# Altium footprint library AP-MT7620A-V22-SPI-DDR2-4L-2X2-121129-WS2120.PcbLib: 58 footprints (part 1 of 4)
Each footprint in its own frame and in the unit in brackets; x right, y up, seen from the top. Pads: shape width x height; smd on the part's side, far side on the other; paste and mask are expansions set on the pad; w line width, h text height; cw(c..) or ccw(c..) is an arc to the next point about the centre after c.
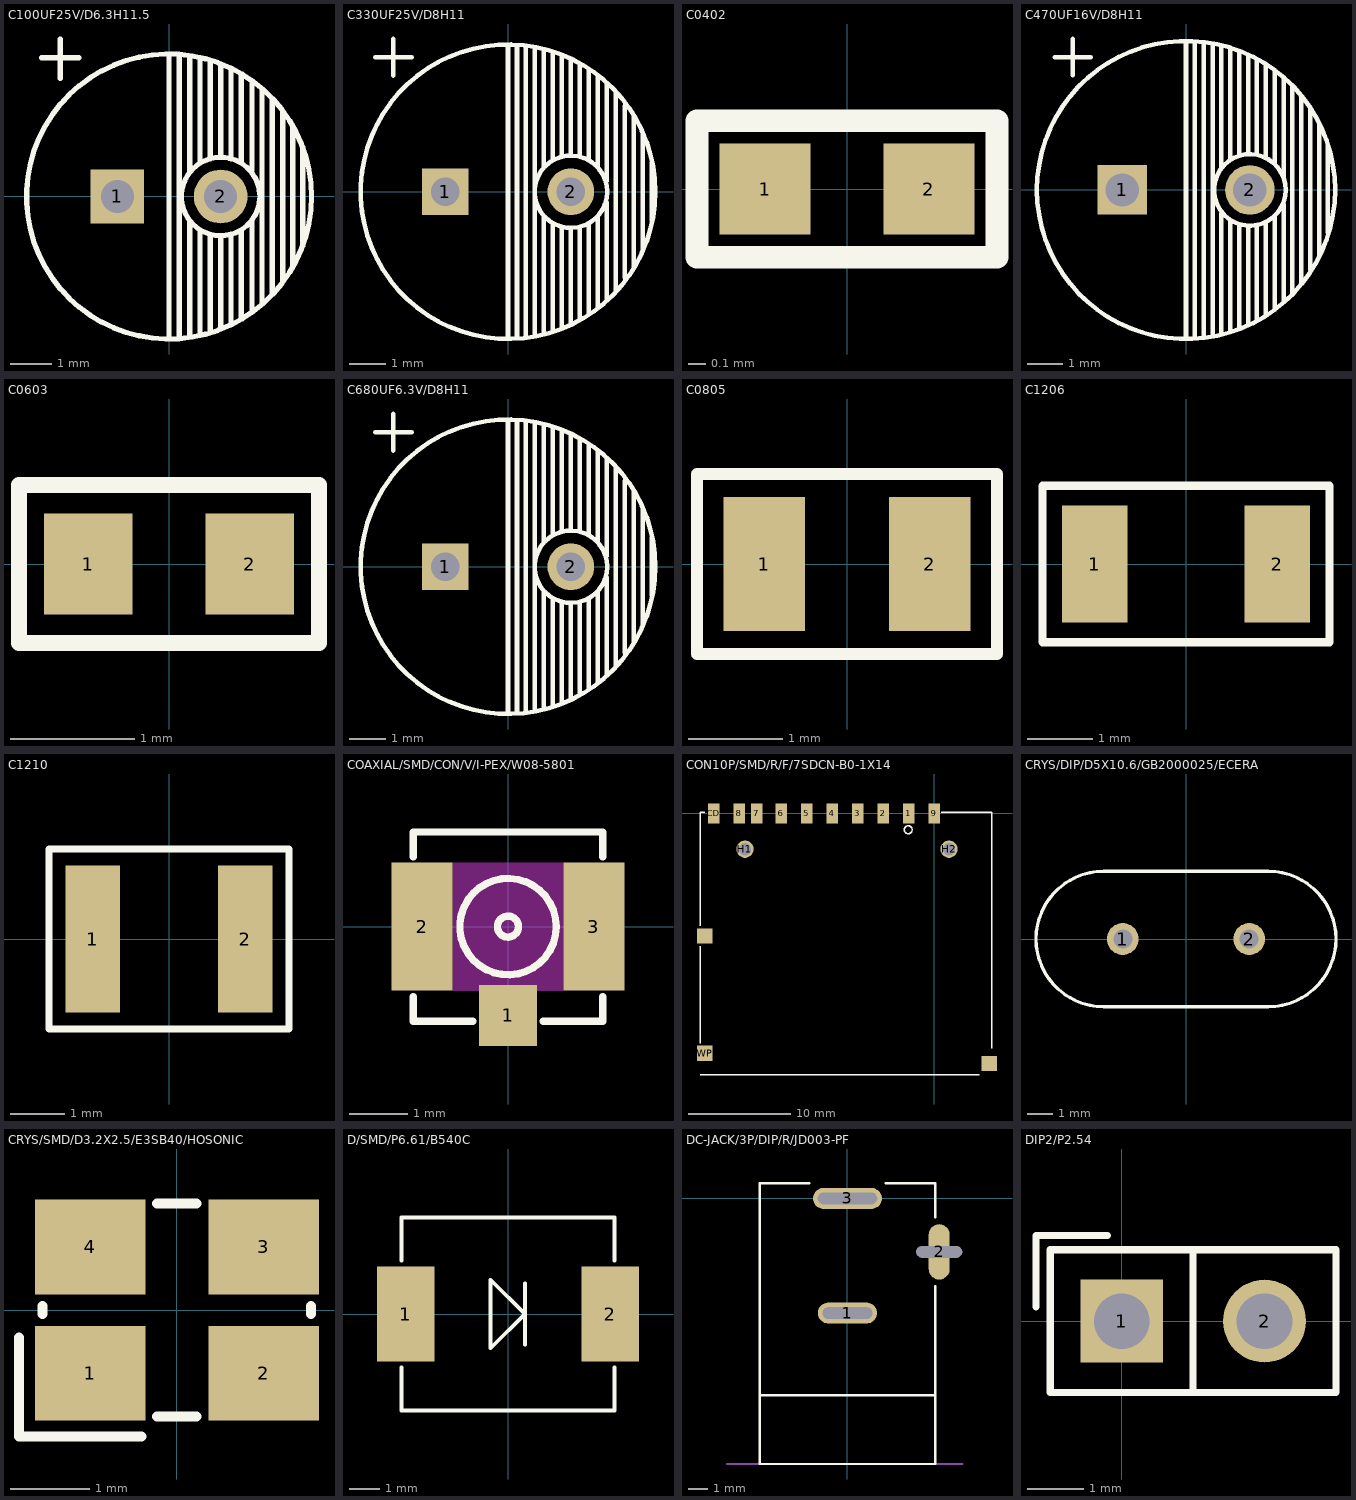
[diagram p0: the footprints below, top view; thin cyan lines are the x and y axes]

## C100UF25V/D6.3H11.5 [mm]
pads (2):
  rect 1.3x1.3 / inner round 1.3 / far side rect 1.3x1.3 hole 0.8: 1(-1.25,0)
  round 1.3 hole 0.8: 2(1.25,0)
Top Overlay:
  circle w0.127: c1.25,0 r0.95
  circle w0.127: c0,0 r3.45
  lines w0.127: -3.081,3.357 -2.181,3.357 ; -2.631,2.863 -2.631,3.813 ; 0,-3.4 0,3.4 ; 0.25,-3.37 0.25,3.37 ; 0.5,-3.35 0.5,-0.635 ; 0.5,0.61 0.5,3.35 ; 0.75,-3.3 0.75,-0.838 ; 0.75,0.838 0.75,3.3 ; 1,-3.25 1,-0.95 ; 1,0.914 1,3.25 ; 1.25,-3.2 1.25,-0.95 ; 1.25,1 1.25,3.2 ; 1.5,-3.1 1.5,-0.914 ; 1.5,0.914 1.5,3.1 ; 1.75,-2.95 1.75,-0.813 ; 1.75,0.813 1.75,2.95 ; 2.008,-2.8 2.008,-0.61 ; 2.008,0.635 2.008,2.8 ; 2.25,-2.55 2.25,2.55 ; 2.5,-2.35 2.5,2.35 ; 2.754,-2.05 2.754,2.05 ; 2.997,-1.7 2.997,1.7 ; 3.237,-1.2 3.237,1.2

## C330UF25V/D8H11 [mm]
pads (2):
  rect 1.3x1.3 / inner round 1.3 / far side rect 1.3x1.3 hole 0.8: 1(-1.75,0)
  round 1.3 hole 0.8: 2(1.75,0)
Top Overlay:
  circle w0.127: c0,0 r4.1
  circle w0.127: c1.75,0 r1.008
  lines w0.127: -3.698,3.745 -2.682,3.745 ; -3.19,3.237 -3.19,4.253 ; 0,-4.08 0,4.08 ; 0.25,-4.05 0.25,4.05 ; 0.5,-4.03 0.5,4.03 ; 0.75,-4 0.75,4 ; 1,-3.95 1,-0.7 ; 1,0.7 1,3.95 ; 1.25,-3.85 1.25,-0.9 ; 1.25,0.9 1.25,3.85 ; 1.5,-3.78 1.5,-1 ; 1.5,1 1.5,3.78 ; 1.75,-3.65 1.75,-1.05 ; 1.75,1.05 1.75,3.65 ; 2,-3.55 2,-1 ; 2,1 2,3.55 ; 2.25,-3.4 2.25,-0.9 ; 2.25,0.9 2.25,3.4 ; 2.5,-3.2 2.5,-0.7 ; 2.5,0.7 2.5,3.2 ; 2.75,-3 2.75,-0.3 ; 2.75,0.3 2.75,3 ; 3,-2.75 3,2.75 ; 3.25,-2.4 3.25,2.4 ; 3.5,-2.1 3.5,2.1 ; 3.75,-1.6 3.75,1.6 ; 4,-0.8 4,0.8

## C0402 [mil]
pads (2):
  rect 20x20 smd: 1(-18,0) 2(18,0)
Top Overlay:
  lines w5: -33,-15 -33,15 33,15 33,-15 -33,-15

## C470UF16V/D8H11 [mil]
pads (2):
  rect 55x55 / inner round 55 / far side rect 55x55 hole 37: 1(-70.87,0)
  round 55 hole 37: 2(70.87,0)
Top Overlay:
  circle w5: c0,0 r165.35
  circle w5: c70.87,0 r39.7
  lines w5: -145.59,147.44 -105.59,147.44 ; -125.59,127.44 -125.59,167.44 ; 0,-165 0,165 ; 9.84,-163.39 9.84,163.39 ; 19.68,-163.39 19.68,163.39 ; 29.53,-161.42 29.53,161.42 ; 39.37,-159.45 39.37,-25.59 ; 39.37,25.59 39.37,159.45 ; 49.21,-157.48 49.21,-33.46 ; 49.21,33.46 49.21,157.48 ; 59.06,-153.54 59.06,-39.37 ; 59.06,39.37 59.06,153.54 ; 68.9,-149.61 68.9,-41.34 ; 68.9,41.34 68.9,149.61 ; 78.74,-143.7 78.74,-39.37 ; 78.74,39.37 78.74,143.7 ; 88.58,-137.8 88.58,-35.43 ; 88.58,35.43 88.58,139.76 ; 98.43,-131.89 98.43,-29.53 ; 98.43,29.53 98.43,131.89 ; 108.27,-124.02 108.27,-15.75 ; 108.27,13.78 108.27,124.02 ; 118.11,-114.17 118.11,114.17 ; 127.95,-102.36 127.95,102.36 ; 137.8,-88.58 137.8,90.55 ; 147.64,-72.83 147.64,72.83 ; 157.48,-47.24 157.48,49.21

## C0603 [mil]
pads (2):
  rect 28x32 smd: 1(-25.59,0) 2(25.59,0)
Top Overlay:
  lines w5: -47.5,-25 47.5,-25 47.5,25 -47.5,25 -47.5,-25

## C680UF6.3V/D8H11 [mm]
pads (2):
  rect 1.3x1.3 / inner round 1.3 / far side rect 1.3x1.3 hole 0.8: 1(-1.75,0)
  round 1.3 hole 0.8: 2(1.75,0)
Top Overlay:
  circle w0.127: c0,0 r4.1
  circle w0.127: c1.75,0 r1.008
  lines w0.127: -3.698,3.745 -2.682,3.745 ; -3.19,3.237 -3.19,4.253 ; 0,-4.08 0,4.08 ; 0.25,-4.05 0.25,4.05 ; 0.5,-4.03 0.5,4.03 ; 0.75,-4 0.75,4 ; 1,-3.95 1,-0.7 ; 1,0.7 1,3.95 ; 1.25,-3.85 1.25,-0.9 ; 1.25,0.9 1.25,3.85 ; 1.5,-3.78 1.5,-1 ; 1.5,1 1.5,3.78 ; 1.75,-3.65 1.75,-1.05 ; 1.75,1.05 1.75,3.65 ; 2,-3.55 2,-1 ; 2,1 2,3.55 ; 2.25,-3.4 2.25,-0.9 ; 2.25,0.9 2.25,3.4 ; 2.5,-3.2 2.5,-0.7 ; 2.5,0.7 2.5,3.2 ; 2.75,-3 2.75,-0.3 ; 2.75,0.3 2.75,3 ; 3,-2.75 3,2.75 ; 3.25,-2.4 3.25,2.4 ; 3.5,-2.1 3.5,2.1 ; 3.75,-1.6 3.75,1.6 ; 4,-0.8 4,0.8

## C0805 [mil]
pads (2):
  rect 34x56 smd: 1(-34.45,0) 2(34.45,0)
Top Overlay:
  lines w5: -62.5,-37.5 62.5,-37.5 62.5,37.5 -62.5,37.5 -62.5,-37.5

## C1206 [mm]
pads (2):
  rect 1x1.8 smd: 1(-1.4,0) 2(1.4,0)
Top Overlay:
  lines w0.127: -2.2,-1.2 2.2,-1.2 2.2,1.2 -2.2,1.2 -2.2,-1.2

## C1210 [mm]
pads (2):
  rect 1x2.7 smd: 1(-1.4,0) 2(1.4,0)
Top Overlay:
  lines w0.127: -2.2,-1.65 2.2,-1.65 2.2,1.65 -2.2,1.65 -2.2,-1.65

## COAXIAL/SMD/CON/V/I-PEX/W08-5801 [mm]
pads (3):
  rect 1x1.05 smd: 1(0,-1.525)
  rect 1.05x2.2 smd: 2(-1.475,0) 3(1.475,0)
Top Overlay:
  circle w0.127: c0,0 r0.18
  circle w0.127: c0,0 r0.828
  lines w0.127: -1.625,-1.2 -1.625,-1.625 -0.6,-1.625 ; -1.625,1.2 -1.625,1.625 1.625,1.625 1.625,1.2 ; 0.6,-1.625 1.625,-1.625 1.625,-1.2
Keep-Out Layer:
  pour cut-out: -0.95,1.1 0.95,1.1 0.95,-1.1 0.5,-1.1 0.5,-1 -0.5,-1 -0.5,-1.1 -0.95,-1.1

## CON10P/SMD/R/F/7SDCN-B0-1X14 [mm]
pads (15):
  rect 1.1x2 smd: 1(-2.5,0) 2(-5,0) 3(-7.5,0) 4(-10,0) 5(-12.5,0) 6(-15,0) 7(-17.4,0) 8(-19.1,0) 9(0,0) CD(-21.6,0)
  rect 1.5x1.5 smd: GND1(-22.5,-12) GND2(5.4,-24.5) WP(-22.5,-23.5)
  round 1.7 hole 1.2 unplated: H1(-18.55,-3.5) H2(1.45,-3.5)
Top Overlay:
  circle w0.127: c-2.548,-1.595 r0.39
  lines w0.127: -22.95,-25.6 4.422,-25.6 ; -22.95,-22.5 -22.95,-13 ; -22.95,-11 -22.95,0.1 -22.5,0.1 ; 0.7,0.1 5.65,0.1 5.65,-23

## CRYS/DIP/D5X10.6/GB2000025/ECERA [mm]
pads (2):
  round 1.23 hole 0.73: 1(-2.44,0) 2(2.44,0)
Top Overlay:
  lines w0.127: -3.175,-2.618 cw(c-3.175,0) -3.175,2.618 3.175,2.618 cw(c3.175,0) 3.175,-2.618 -3.097,-2.618 -3.175,-2.618

## CRYS/SMD/D3.2X2.5/E3SB40/HOSONIC [mm]
pads (4):
  rect 1.4x1.2 smd: 1(-1.1,-0.8) 2(1.1,-0.8) 3(1.1,0.8) 4(-1.1,0.8)
Top Overlay:
  lines w0.127: -2,-0.35 -2,-1.6 -0.45,-1.6 ; -1.7,-0.05 -1.7,0.05 ; -0.25,-1.35 0.25,-1.35 ; -0.25,1.35 0.25,1.35 ; 1.7,-0.05 1.7,0.05

## D/SMD/P6.61/B540C [mm]
pads (2):
  rect 1.92x3.18 smd: 1(-3.405,0) 2(3.405,0)
Top Overlay:
  lines w0.127: -3.55,-1.778 -3.55,-3.21 3.55,-3.21 3.55,-1.778 ; -3.55,1.778 -3.55,3.21 3.55,3.21 3.55,1.778 ; 0.562,-1.016 0.562,1.016 ; -0.581,-1.143 0.562,0 -0.581,1.143 -0.581,-1.143

## DC-JACK/3P/DIP/R/JD003-PF [mm]
pads (3):
  oval 3.1x1.1 hole 0.6 slot 2.6 at 0 deg: 1(0,-6)
  oval 1.1x2.9 hole 0.6 slot 2.4 at 0 deg: 2(4.8,-2.8)
  oval 3.6x1.1 hole 0.6 slot 3.1 at 0 deg: 3(0,0)
Top Overlay:
  lines w0.127: -4.6,-10.3 4.6,-10.3 ; -2,0.8 -4.6,0.8 -4.6,-13.9 4.6,-13.9 4.6,-4.6 ; 2,0.8 4.6,0.8 4.6,-1
Mechanical 16:
  lines w0.127: -6.3,-13.9 6,-13.9

## DIP2/P2.54 [mil]
pads (2):
  rect 58x58 hole 39: 1(0,0)
  round 58 hole 39: 2(100,0)
Top Overlay:
  lines w5: -60,10 -60,60 -10,60 ; 50,-50 50,50 ; -50,-50 150,-50 150,50 -50,50 -50,-50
